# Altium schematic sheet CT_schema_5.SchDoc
size 296 x 173 mm
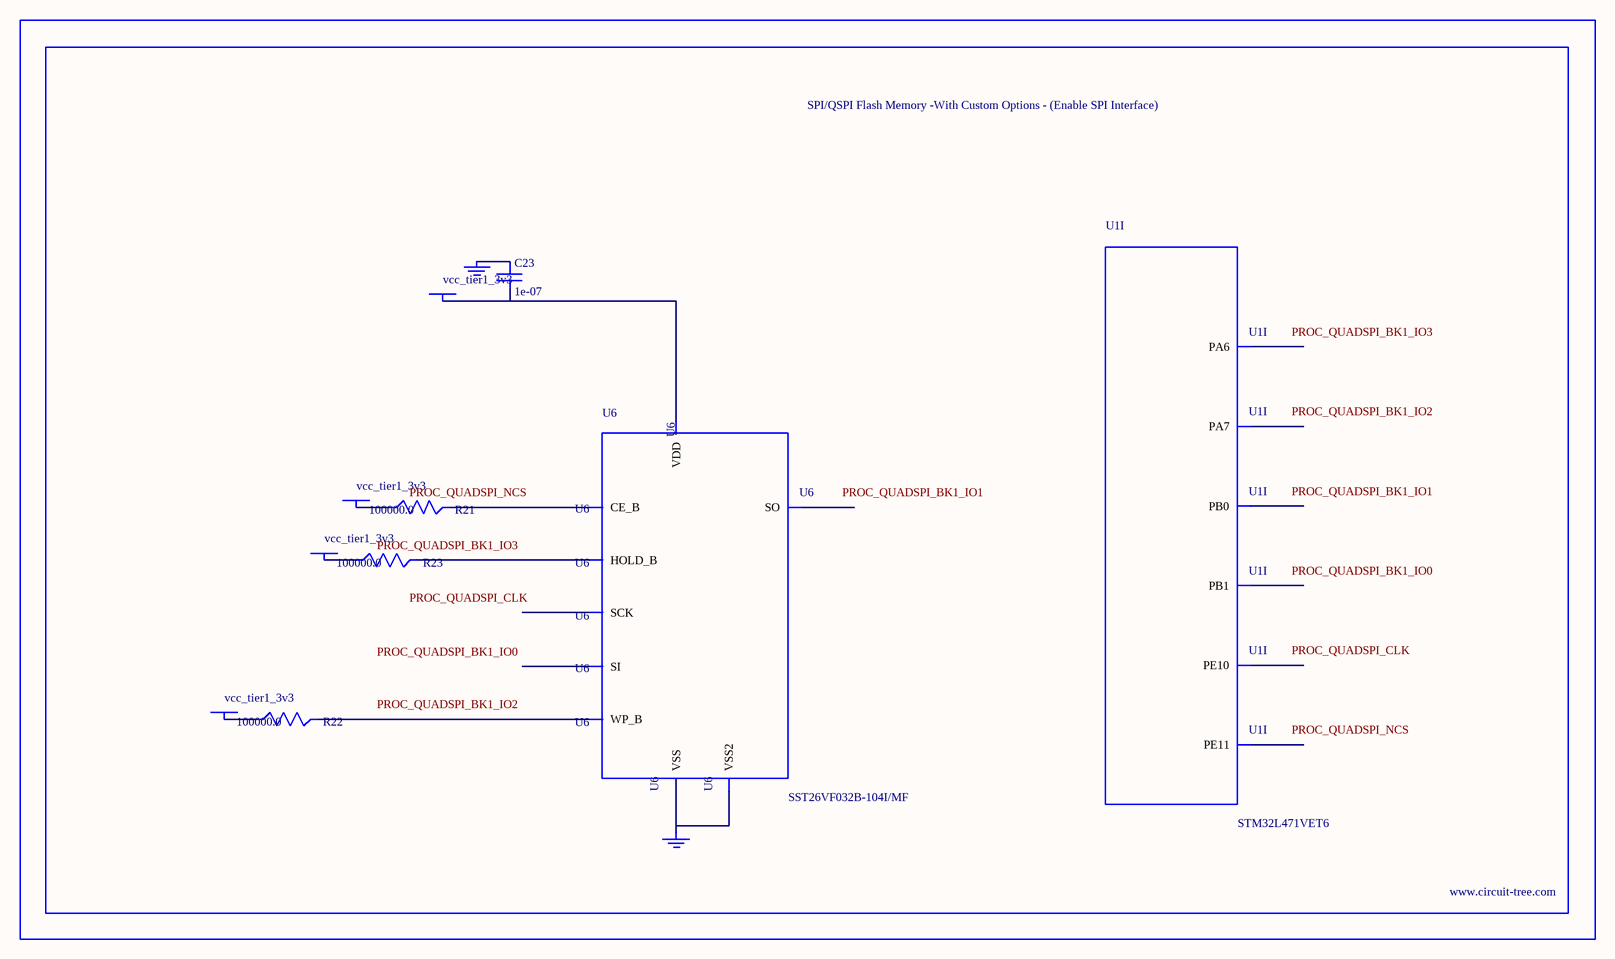
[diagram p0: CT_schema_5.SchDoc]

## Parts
BORDER4  (no value)
C23  1e-07  [C0402]
GND_INSTANCE_4_0  (no value)
GND_INSTANCE_4_1  (no value)
POWER_INSTANCE_4_0  vcc_tier1_3v3
POWER_INSTANCE_4_1  vcc_tier1_3v3
POWER_INSTANCE_4_2  vcc_tier1_3v3
POWER_INSTANCE_4_3  vcc_tier1_3v3
R21  100000.0  [R0603]
R22  100000.0  [R0603]
R23  100000.0  [R0603]
U1  STM32L471VET6  [LQFP100]  (part I of 11)
U6  SST26VF032B-104I/MF  [WFDN-8]

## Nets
NetC23_1: C23.1 GND_INSTANCE_4_0.0(GND)
NetC23_2: C23.2 POWER_INSTANCE_4_3.0(PWR) U6.8(VDD)
NetGND_INSTANCE_4_1_0: GND_INSTANCE_4_1.0(GND) U6.4(VSS) U6.9(VSS2)
NetPOWER_INSTANCE_4_0_0: POWER_INSTANCE_4_0.0(PWR) R21.1
NetPOWER_INSTANCE_4_1_0: POWER_INSTANCE_4_1.0(PWR) R22.1
NetPOWER_INSTANCE_4_2_0: POWER_INSTANCE_4_2.0(PWR) R23.1
NetR21_2: R21.2 U6.1(CE_B)
NetR22_2: R22.2 U6.3(WP_B)
NetR23_2: R23.2 U6.7(HOLD_B)

Not connected (* = marked no-connect by the designer): U1 31(PA6) 32(PA7) 35(PB0) 36(PB1) 41(PE10) 42(PE11); U6 2(SO) 5(SI) 6(SCK)

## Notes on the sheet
- Labels drawn without touching a wire or pin: PROC_QUADSPI_BK1_IO0, PROC_QUADSPI_BK1_IO1, PROC_QUADSPI_BK1_IO2, PROC_QUADSPI_BK1_IO3, PROC_QUADSPI_CLK, PROC_QUADSPI_NCS

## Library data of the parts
BORDER4 = BORDER_PAGE4
C23 = C0402C104K3RACTU
GND_INSTANCE_4_0 GND_INSTANCE_4_1 = GND
POWER_INSTANCE_4_0-POWER_INSTANCE_4_3 = PWR
R21-R23 = RC0603JR-07100KL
